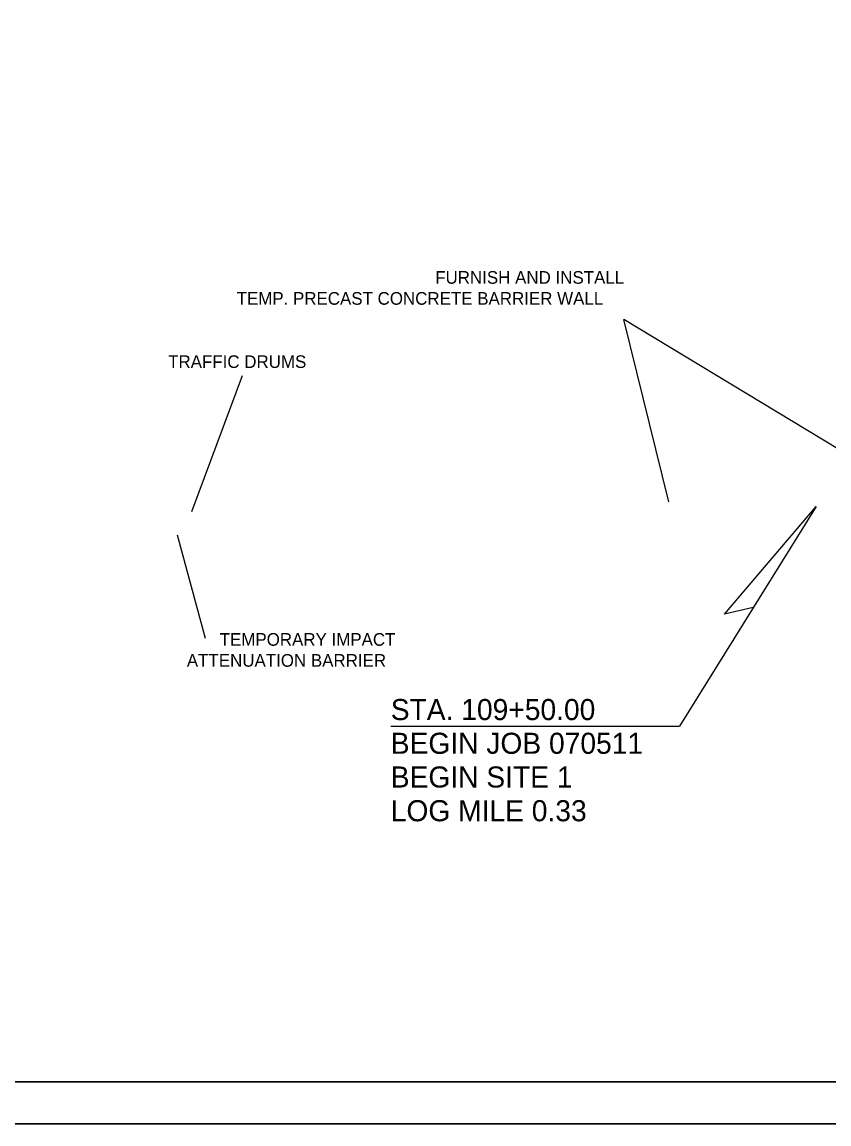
# Model space of a CAD drawing. Extents: x 1398460 to 1408037, y 380768 to 383968.
# Drawn here: x 1401127 to 1401509, y 381834 to 382357 of the extents above; entities that cross this region are included whole.
import ezdxf

# ---------------------------------------------------------------- set-up
doc = ezdxf.new("R2010")
doc.units = 0
for name, color, linetype in [('Default', 7, 'Continuous'), ('MOT STAGE ALL', 7, 'Continuous'), ('R_Border', 7, 'Continuous'), ('R_Dimension', 7, 'Continuous'), ('R_MOT', 7, 'Continuous'), ('R_No Plot', 7, 'Continuous')]:
    doc.layers.add(name, color=color, linetype=linetype)

msp = doc.modelspace()

# ---------------------------------------------------------------- linework, layer by layer
at = {"layer": 'Default'}
for p in [(1401503.27, 382127.13), (1401301.56, 382022.93)]:
    msp.add_line(p, (1401438.43, 382022.93), dxfattribs=at)
msp.add_lwpolyline([(1401473.5, 382079.29), (1401459.83, 382076.17), (1401503.27, 382127.13)], dxfattribs=at)
at = {"layer": 'R_Border'}
msp.add_line((1402308.47, 381854.12), (1400727.57, 381854.12), dxfattribs=at)
at = {"layer": 'R_Dimension'}
msp.add_line((1401231.04, 382189.15), (1401206.98, 382124.72), dxfattribs=at)
at = {"layer": 'R_MOT'}
for p, q in [((1401433.36, 382129.46), (1401412.13, 382215.9)), ((1401530.15, 382144.56), (1401412.13, 382215.9)), ((1401200.18, 382113.81), (1401213.46, 382064.74))]:
    msp.add_line(p, q, dxfattribs=at)
at = {"layer": 'R_No Plot'}
msp.add_line((1400665.56, 381834.22), (1402332.23, 381834.22), dxfattribs=at)
for points in [[(1400665.53, 382900.89), (1402332.23, 382900.89), (1402332.23, 381834.2), (1400665.53, 381834.2)], [(1400727.57, 382881.42), (1400727.57, 381854.12), (1402308.47, 381854.12), (1402308.47, 382710.36), (1402191.82, 382710.36), (1402191.82, 382832.02), (1401995.27, 382832.02), (1401995.27, 382881.42)], [(1401897.17, 382881.42), (1401995.27, 382881.42), (1401995.27, 382832.02), (1402075.83, 382832.02), (1402191.82, 382832.02), (1402191.82, 382710.36), (1402308.47, 382710.36), (1402308.47, 381854.12), (1400727.57, 381854.12), (1400727.57, 382881.42)], [(1400727.57, 381854.12), (1400727.57, 382367.77), (1402308.47, 382367.77), (1402308.47, 381854.12)]]:
    msp.add_lwpolyline(points, close=True, dxfattribs=at)

# ---------------------------------------------------------------- texts
at = {"layer": 'MOT STAGE ALL'}
for s, p in [('FURNISH AND INSTALL', (1401322.64, 382232.91)), (' TEMP. PRECAST CONCRETE BARRIER WALL', (1401226.22, 382222.95)), ('TEMPORARY IMPACT', (1401220.42, 382061.13)), (' ATTENUATION BARRIER', (1401202.61, 382051.17))]:
    msp.add_text(s, height=6.0001, rotation=0, dxfattribs=at).set_placement(p)
at = {"layer": 'R_Border'}
msp.add_text('TRAFFIC DRUMS', height=6, dxfattribs=at).set_placement((1401195.98, 382192.94))
at = {"layer": 'R_Dimension'}
for s, p in [('STA. 109+50.00', (1401301.56, 382025.85)), ('BEGIN JOB 070511', (1401301.56, 382009.85)), ('BEGIN SITE 1', (1401301.56, 381993.85)), ('LOG MILE 0.33', (1401301.56, 381977.85))]:
    msp.add_text(s, height=10, dxfattribs=at).set_placement(p)

doc.saveas('drawing.dxf')
